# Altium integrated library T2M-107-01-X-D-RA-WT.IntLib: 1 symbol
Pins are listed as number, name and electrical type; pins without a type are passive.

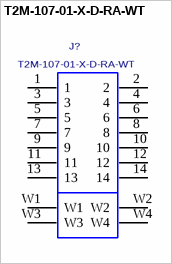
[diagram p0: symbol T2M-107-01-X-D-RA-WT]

## T2M-107-01-X-D-RA-WT
designator J?
2MM PITCH SHROUDED RIGHT ANGLE TERMINAL STRIP.; MANUFACTURER: SAMTEC
footprint T2M-107-01-X-D-RA-WT
pins: 1, 2, 3, 4, 5, 6, 7, 8, 9, 10, 11, 12, 13, 14, W1, W2, W3, W4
